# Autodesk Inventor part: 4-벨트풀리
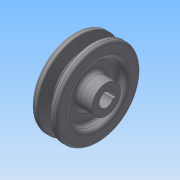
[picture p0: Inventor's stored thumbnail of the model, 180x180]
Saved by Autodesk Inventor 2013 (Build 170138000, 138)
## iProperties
Created: 2015-02
Part Number: 4-벨트풀리
Material: 일반
Document SubType Name: Modeling
Designer: Administrator
Density: 1 g/cm^3
Author: Administrator
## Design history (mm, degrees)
sketch "스케치1"
  geometry: L1 (0, 0)-(25, 0); L2 (0, 5.5)-(0, 11); L3 (0, 11)-(6, 11); L4 (6, 11)-(6, 21.5); L5 (6, 21.5)-(0, 21.5); L6 (0, 21.5)-(0, 32.5); L7 (0, 32.5)-(4.675, 32.5); L8 (4.675, 32.5)-(7.426, 23.5); L9 (7.426, 23.5)-(11.574, 23.5); L10 (11.574, 23.5)-(14.325, 32.5); L11 (14.325, 32.5)-(19, 32.5); L12 (19, 32.5)-(19, 21.5); L13 (19, 21.5)-(13, 21.5); L14 (13, 21.5)-(13, 11); L15 (13, 11)-(25, 11); L16 (25, 11)-(25, 5.5); L17 (25, 5.5)-(0, 5.5); 2 further points
  constraints: 34 end point, 10 parallel, 6 collinear, 4 point on line, 3 equal length, 2 perpendicular, 1 horizontal, 1 horizontal alignment
  dimensions: "d0" = 25 distance of L1.start L1.end; "d1" = 34 deg angle of L10 L8; "d2" = 2.7 distance from line of point (5.5, 29.8) L7; "d3" = 6.3 distance from line of L9 point (5.5, 29.8); "d4" = 19 distance between parallel lines of L12 L6; "d5" = 8 distance of point (13.5, 29.8) point (5.5, 29.8); "d6" = 22 diameter of L15 L1; "d7" = 11 diameter of L17 L1; "d8" = 6 distance of L4.end L5.end; "d9" = 43 diameter of L5 L1; "d10" = 65 diameter of L7 L1
revolve "회전1" sketch "스케치1" stored, may be unused: angle "d11" = 90 deg
sketch "스케치2"
  geometry: L1 (-2, 5.123)-(-2, 7.3); L2 (-2, 7.3)-(2, 7.3); L3 (2, 7.3)-(2, 5.123); A1 r 5.5 centre (0, 0) between (-2, 5.123) and (2, 5.123) reference
  constraints: 6 end point, 2 parallel, 2 point on circle, 1 perpendicular, 1 vertical
  dimensions: "d12" = 4 distance of L1.end L2.end; "d14" = 12.8 dimension on A1 L2
extrude "돌출1" cut sketch "스케치2" stored distance "d15" = 10; taper "d16" = 0 deg
fillet "모깎기1" dims "d17" = 1, "d18" = 0.5, "d19" = 2
fillet "모깎기2" dims "d20" = 3
node "솔리드1"
